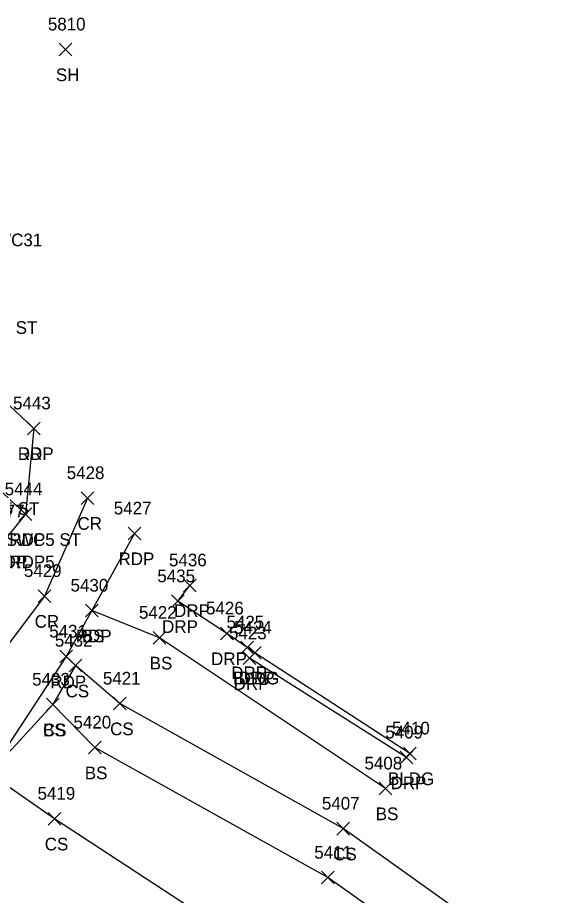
# Model space of a CAD drawing. Extents: x 1618146 to 1620418, y 640749 to 641927.
# Drawn here: x 1620245.8 to 1620332.3, y 641136.7 to 641275.2 of the extents above; entities that cross this region are included whole.
import ezdxf

# ---------------------------------------------------------------- set-up
doc = ezdxf.new("R2010")
doc.units = 0
for name, color, linetype in [('L_A', 7, 'Continuous'), ('L_I', 7, 'Continuous'), ('L_TIC', 7, 'Continuous'), ('LBC', 7, 'Continuous'), ('LELB', 7, 'Continuous'), ('P_A', 7, 'Continuous'), ('P_I', 7, 'Continuous'), ('P_TIC', 7, 'Continuous'), ('PET', 7, 'Continuous'), ('PRC', 7, 'Continuous'), ('R_A', 7, 'Continuous'), ('R_I', 7, 'Continuous'), ('R_TIC', 7, 'Continuous'), ('RDP', 7, 'Continuous'), ('RSW', 7, 'Continuous')]:
    doc.layers.add(name, color=color, linetype=linetype)

msp = doc.modelspace()

# ---------------------------------------------------------------- linework, layer by layer
at = {"layer": 'L_TIC'}
for points in [[(1620252.38, 641269.21), (1620254.38, 641271.21)], [(1620254.38, 641269.21), (1620252.38, 641271.21)], [(1620256.52, 641180.67), (1620258.52, 641182.67)], [(1620258.52, 641180.67), (1620256.52, 641182.67)], [(1620267.23, 641176.38), (1620269.23, 641178.38)], [(1620269.23, 641176.38), (1620267.23, 641178.38)], [(1620282.23, 641174.02), (1620284.23, 641176.02)], [(1620284.23, 641174.02), (1620282.23, 641176.02)], [(1620253.96, 641171.98), (1620255.96, 641173.98)], [(1620255.96, 641171.98), (1620253.96, 641173.98)], [(1620250.38, 641165.83), (1620252.38, 641167.83)], [(1620252.38, 641165.83), (1620250.38, 641167.83)], [(1620250.38, 641165.83), (1620252.38, 641167.83)], [(1620252.38, 641165.83), (1620250.38, 641167.83)], [(1620260.97, 641166), (1620262.97, 641168)], [(1620262.97, 641166), (1620260.97, 641168)], [(1620256.99, 641159.06), (1620258.99, 641161.06)], [(1620258.99, 641159.06), (1620256.99, 641161.06)], [(1620306.68, 641158.13), (1620308.68, 641160.13)], [(1620308.68, 641158.13), (1620306.68, 641160.13)], [(1620302.89, 641152.6), (1620304.89, 641154.6)], [(1620304.89, 641152.6), (1620302.89, 641154.6)], [(1620250.67, 641147.83), (1620252.67, 641149.83)], [(1620252.67, 641147.83), (1620250.67, 641149.83)], [(1620296.17, 641146.26), (1620298.17, 641148.26)], [(1620298.17, 641146.26), (1620296.17, 641148.26)], [(1620293.75, 641138.53), (1620295.75, 641140.53)], [(1620295.75, 641138.53), (1620293.75, 641140.53)]]:
    msp.add_lwpolyline(points, dxfattribs=at)
at = {"layer": 'LBC'}
msp.add_lwpolyline([(1620307.68, 641159.13), (1620283.23, 641175.02)], dxfattribs=at)
at = {"layer": 'LELB'}
for points in [[(1620303.89, 641153.6), (1620268.23, 641177.38), (1620257.52, 641181.67)], [(1620322.25, 641104.58), (1620328.73, 641115.39), (1620332.25, 641122.24), (1620297.17, 641147.26), (1620261.97, 641167), (1620254.96, 641172.98), (1620251.38, 641166.83), (1620241.33, 641155.99)], [(1620328.73, 641115.39), (1620294.75, 641139.53), (1620257.99, 641160.06), (1620251.38, 641166.83)], [(1620310.49, 641089.31), (1620322.25, 641104.58), (1620287.41, 641125.43), (1620251.67, 641148.83), (1620241.33, 641155.99)]]:
    msp.add_lwpolyline(points, dxfattribs=at)
at = {"layer": 'P_TIC'}
for points in [[(1620247.37, 641209.42), (1620249.37, 641211.42)], [(1620249.37, 641209.42), (1620247.37, 641211.42)], [(1620255.84, 641198.42), (1620257.84, 641200.42)], [(1620257.84, 641198.42), (1620255.84, 641200.42)], [(1620246.05, 641195.87), (1620248.05, 641197.87)], [(1620248.05, 641195.87), (1620246.05, 641197.87)], [(1620263.26, 641192.84), (1620265.26, 641194.84)], [(1620265.26, 641192.84), (1620263.26, 641194.84)], [(1620249.09, 641182.97), (1620251.09, 641184.97)], [(1620251.09, 641182.97), (1620249.09, 641184.97)], [(1620256.52, 641180.67), (1620258.52, 641182.67)], [(1620258.52, 641180.67), (1620256.52, 641182.67)], [(1620252.5, 641173.42), (1620254.5, 641175.42)], [(1620254.5, 641173.42), (1620252.5, 641175.42)]]:
    msp.add_lwpolyline(points, dxfattribs=at)
at = {"layer": 'PET'}
for points in [[(1620248.37, 641210.42), (1620247.05, 641196.87), (1620244.22, 641193.36), (1620231.18, 641173.76), (1620213.38, 641155.49), (1620202.4, 641145.53), (1620184.69, 641164.4), (1620181.46, 641166.89), (1620163.82, 641184.39), (1620152.3, 641193.8)], [(1620264.26, 641193.84), (1620257.52, 641181.67), (1620253.5, 641174.42), (1620241.33, 641155.99), (1620224.76, 641135.64), (1620223.78, 641130.07), (1620229.04, 641107.52), (1620237.42, 641090.89)]]:
    msp.add_lwpolyline(points, dxfattribs=at)
at = {"layer": 'PRC'}
msp.add_lwpolyline([(1620256.84, 641199.42), (1620250.09, 641183.97), (1620236.84, 641166.4), (1620223.56, 641150.86), (1620213.75, 641137.81), (1620205.8, 641118.71)], dxfattribs=at)
at = {"layer": 'R_TIC'}
for points in [[(1620247.37, 641209.42), (1620249.37, 641211.42)], [(1620249.37, 641209.42), (1620247.37, 641211.42)], [(1620246.05, 641195.87), (1620248.05, 641197.87)], [(1620248.05, 641195.87), (1620246.05, 641197.87)], [(1620272.02, 641184.65), (1620274.02, 641186.65)], [(1620274.02, 641184.65), (1620272.02, 641186.65)], [(1620270.13, 641182.14), (1620272.13, 641184.14)], [(1620272.13, 641182.14), (1620270.13, 641184.14)], [(1620277.86, 641177.06), (1620279.86, 641179.06)], [(1620279.86, 641177.06), (1620277.86, 641179.06)], [(1620281.04, 641174.85), (1620283.04, 641176.85)], [(1620283.04, 641174.85), (1620281.04, 641176.85)], [(1620282.23, 641174.02), (1620284.23, 641176.02)], [(1620284.23, 641174.02), (1620282.23, 641176.02)], [(1620281.43, 641173.14), (1620283.43, 641175.14)], [(1620283.43, 641173.14), (1620281.43, 641175.14)], [(1620306.18, 641157.49), (1620308.18, 641159.49)], [(1620308.18, 641157.49), (1620306.18, 641159.49)]]:
    msp.add_lwpolyline(points, dxfattribs=at)
at = {"layer": 'RDP'}
for points in [[(1620227.27, 641230.33), (1620248.37, 641210.42)], [(1620307.18, 641158.49), (1620282.43, 641174.14), (1620283.23, 641175.02), (1620282.04, 641175.85), (1620278.86, 641178.06), (1620271.13, 641183.14), (1620273.02, 641185.65)]]:
    msp.add_lwpolyline(points, dxfattribs=at)
at = {"layer": 'RSW'}
msp.add_lwpolyline([(1620247.05, 641196.87), (1620241.81, 641201.77), (1620221.01, 641223.74), (1620217.69, 641227.23), (1620214.97, 641229.37), (1620205.98, 641235.71)], dxfattribs=at)

# ---------------------------------------------------------------- texts
at = {"layer": 'L_A'}
for s, p in [('SH', (1620251.87, 641265.21)), ('BS', (1620255.96, 641176.67)), ('BS', (1620266.67, 641172.38)), ('BLDG', (1620279.82, 641170.02)), ('CS', (1620253.4, 641167.98)), ('CS', (1620249.83, 641161.83)), ('BS', (1620249.83, 641161.83)), ('CS', (1620260.42, 641162)), ('BS', (1620256.43, 641155.06)), ('BLDG', (1620304.27, 641154.13)), ('BS', (1620302.33, 641148.6)), ('CS', (1620250.11, 641143.83)), ('CS', (1620295.61, 641142.26))]:
    msp.add_text(s, height=2, dxfattribs=at).set_placement(p)
at = {"layer": 'L_I'}
for s, p in [('5810', (1620250.6, 641273.21)), ('5430', (1620254.18, 641184.67)), ('5422', (1620264.97, 641180.38)), ('5424', (1620279.97, 641178.02)), ('5432', (1620251.7, 641175.98)), ('5433', (1620248.12, 641169.83)), ('5433', (1620248.12, 641169.83)), ('5421', (1620259.28, 641170)), ('5420', (1620254.64, 641163.06)), ('5410', (1620304.9, 641162.13)), ('5408', (1620300.55, 641156.6)), ('5419', (1620248.97, 641151.83)), ('5407', (1620293.83, 641150.26)), ('5411', (1620292.63, 641142.53))]:
    msp.add_text(s, height=2, dxfattribs=at).set_placement(p)
at = {"layer": 'P_A'}
for s, p in [('RDP', (1620245.86, 641205.42)), ('CR', (1620255.28, 641194.42)), ('RDP', (1620244.54, 641191.87)), ('RDP', (1620261.75, 641188.84)), ('RDP', (1620241.71, 641188.36)), ('CR', (1620248.52, 641178.97)), ('RDP', (1620255.01, 641176.67)), ('RDP', (1620250.99, 641169.42))]:
    msp.add_text(s, height=2, dxfattribs=at).set_placement(p)
at = {"layer": 'P_I'}
for s, p in [('5443', (1620245.11, 641213.42)), ('5428', (1620253.58, 641202.42)), ('5444', (1620243.79, 641199.87)), ('5477', (1620240.96, 641196.36)), ('5427', (1620261, 641196.84)), ('5429', (1620246.82, 641186.97)), ('5430', (1620254.18, 641184.67)), ('5431', (1620250.81, 641177.42))]:
    msp.add_text(s, height=2, dxfattribs=at).set_placement(p)
at = {"layer": 'R_A'}
for s, p in [('DRP3 SWC31', (1620232.62, 641239.16)), ('SWC3 ST SWC ST DRP33 ST SWC31 ST', (1620198.27, 641225.33)), ('SWC3 ST SWC ST DRP33 ST SWC31 ST', (1620198.27, 641225.33)), ('SWC3 ST SWC ST DRP33 ST SWC31 ST', (1620198.27, 641225.33)), ('DRP', (1620245.86, 641205.42)), ('SWC5 TS5 ST', (1620231.74, 641196.77)), ('RDP5 SWC5 ST', (1620236.07, 641191.87)), ('SWC5 RDP5', (1620236.06, 641188.36)), ('DRP', (1620270.51, 641180.65)), ('DRP', (1620268.62, 641178.14)), ('DRP', (1620276.35, 641173.06)), ('DRP', (1620279.53, 641170.85)), ('DRP', (1620280.71, 641170.02)), ('DRP', (1620279.91, 641169.14)), ('DRP', (1620304.67, 641153.49))]:
    msp.add_text(s, height=2, dxfattribs=at).set_placement(p)
at = {"layer": 'R_I'}
for s, p in [('5443', (1620245.11, 641213.42)), ('5444', (1620243.79, 641199.87)), ('5477', (1620240.96, 641196.36)), ('5436', (1620269.71, 641188.65)), ('5435', (1620267.87, 641186.14)), ('5426', (1620275.55, 641181.06)), ('5425', (1620278.78, 641178.85)), ('5424', (1620279.97, 641178.02)), ('5423', (1620279.17, 641177.14)), ('5409', (1620303.83, 641161.49))]:
    msp.add_text(s, height=2, dxfattribs=at).set_placement(p)

doc.saveas('drawing.dxf')
